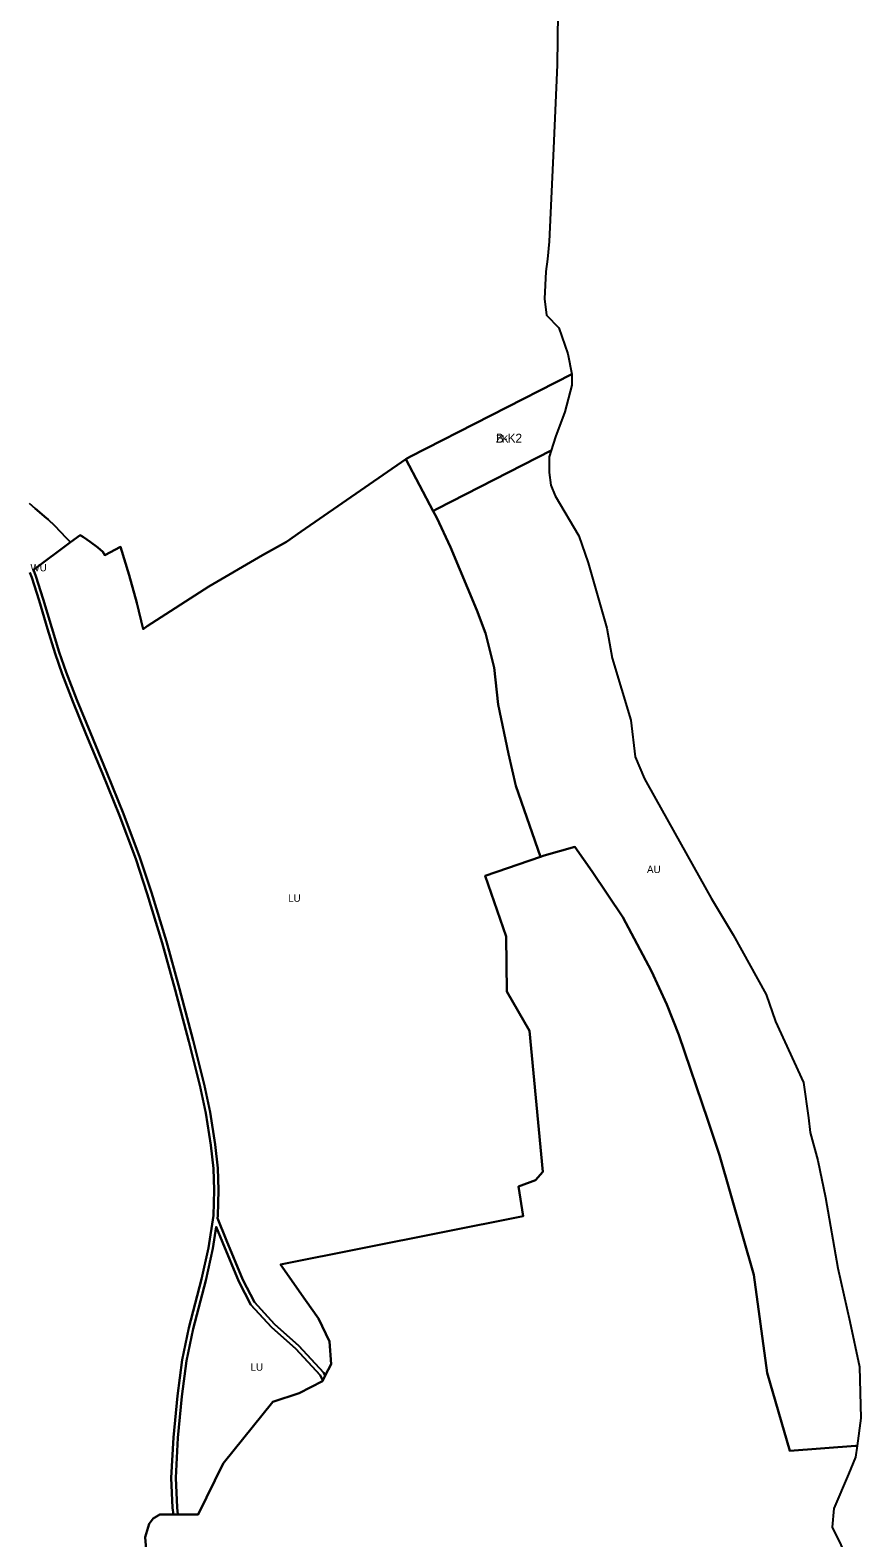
# Model space of a CAD drawing. Extents: x -532067 to -529270, y -1180561 to -1176456.
# Drawn here: x -530157 to -529591, y -1180006 to -1178979 of the extents above; entities that cross this region are included whole.
import ezdxf

# ---------------------------------------------------------------- set-up
doc = ezdxf.new("R2010")
doc.units = 0
for name, color, linetype in [('90630013', 7, 'Continuous'), ('90710023', 7, 'Continuous'), ('90730013', 7, 'Continuous'), ('90750013', 7, 'Continuous'), ('90770013', 7, 'Continuous'), ('ID_navrh', 7, 'Continuous')]:
    doc.layers.add(name, color=color, linetype=linetype)

msp = doc.modelspace()

# ---------------------------------------------------------------- linework, layer by layer
at = {"layer": '90630013'}
msp.add_lwpolyline([(-530157.9403, -1179301.39145), (-530153.9193, -1179304.64945), (-530151.1353, -1179307.13145), (-530147.5963, -1179310.16545), (-530145.0753, -1179312.33345), (-530140.6333, -1179316.66945), (-530132.8283, -1179324.73845), (-530129.9333, -1179327.73145), (-530155.1743, -1179346.45045), (-530153.5473, -1179350.79245), (-530148.4673, -1179366.46045), (-530142.7323, -1179386.00945), (-530137.6503, -1179402.66845), (-530132.8233, -1179416.41845), (-530125.5443, -1179435.13045), (-530116.4203, -1179457.56345), (-530105.4193, -1179484.13845), (-530093.7863, -1179512.92945), (-530082.6913, -1179542.63745), (-530074.7343, -1179566.39445), (-530064.6193, -1179599.92445), (-530055.7123, -1179632.12945), (-530046.3623, -1179667.39345), (-530038.9243, -1179697.16745), (-530034.8343, -1179716.32245), (-530031.2413, -1179738.26245), (-530029.5813, -1179754.37545), (-530028.9503, -1179769.45045), (-530029.5843, -1179786.84445), (-530029.8413, -1179788.59645), (-530023.5823, -1179803.73845), (-530012.5283, -1179830.47545), (-530004.4723, -1179845.81445), (-529990.8993, -1179860.67845), (-529974.2853, -1179875.42845), (-529957.5543, -1179893.62445), (-529956.3333, -1179895.84545), (-529958.0503, -1179899.12645), (-529959.1613, -1179896.89645), (-529959.7993, -1179895.61645), (-529976.3913, -1179877.57045), (-529993.0093, -1179862.81845), (-530006.9483, -1179847.55245), (-530015.2483, -1179831.74945), (-530026.3543, -1179804.88445), (-530030.6903, -1179794.39445), (-530032.8693, -1179809.26545), (-530037.7973, -1179830.89445), (-530046.2823, -1179864.04145), (-530050.8573, -1179885.68545), (-530054.0183, -1179910.00545), (-530056.7063, -1179938.14145), (-530058.2353, -1179965.53245), (-530057.3423, -1179985.65445), (-530056.7433, -1179990.50045), (-530059.7683, -1179990.48145), (-530060.3343, -1179985.90445), (-530061.2393, -1179965.51445), (-530059.6983, -1179937.91545), (-530057.0003, -1179909.66945), (-530053.8173, -1179885.18145), (-530049.2043, -1179863.35945), (-530040.7133, -1179830.18845), (-530035.8213, -1179808.71345), (-530032.5763, -1179786.57245), (-530031.9523, -1179769.45845), (-530032.5753, -1179754.59145), (-530034.2173, -1179738.65845), (-530037.7823, -1179716.87845), (-530041.8483, -1179697.84545), (-530049.2683, -1179668.14145), (-530058.6083, -1179632.91345), (-530067.5013, -1179600.75845), (-530077.5943, -1179567.30445), (-530085.5193, -1179543.63945), (-530096.5823, -1179514.01545), (-530108.1953, -1179485.27445), (-530119.1963, -1179458.70145), (-530128.3323, -1179436.23845), (-530135.6373, -1179417.45845), (-530140.5023, -1179403.60245), (-530145.6063, -1179386.86945), (-530151.3333, -1179367.34645), (-530156.3793, -1179351.78245), (-530157.6823, -1179348.30645)], dxfattribs=at)
at = {"layer": '90710023'}
msp.add_lwpolyline([(-529802.1983, -1179265.11945), (-529879.9973, -1179304.96045), (-529882.5483, -1179306.33145), (-529882.7653, -1179306.44845), (-529901.4753, -1179271.09245), (-529898.5783, -1179269.53645), (-529788.3023, -1179213.06445), (-529788.3023, -1179220.72845), (-529793.0853, -1179238.91945), (-529799.2923, -1179255.84645)], close=True, dxfattribs=at)
at = {"layer": '90730013'}
msp.add_lwpolyline([(-530073.5353, -1180073.74245), (-530079.0333, -1180006.03545), (-530076.2843, -1179996.88545), (-530073.5353, -1179993.22645), (-530068.9533, -1179990.48145), (-530059.7903, -1179990.48145), (-530059.7683, -1179990.48145), (-530056.7433, -1179990.50045), (-530042.9493, -1179990.59045), (-530025.8873, -1179955.71245), (-529992.1313, -1179913.72845), (-529973.9833, -1179907.85145), (-529958.2653, -1179899.53745), (-529958.0503, -1179899.12645), (-529956.3333, -1179895.84545), (-529952.2643, -1179888.07045), (-529953.3483, -1179872.56745), (-529960.9023, -1179856.89545), (-529969.6583, -1179844.49445), (-529986.8263, -1179820.03945), (-529821.3803, -1179787.17945), (-529824.6333, -1179766.87845), (-529812.8943, -1179762.56045), (-529808.0913, -1179756.82645), (-529817.0733, -1179660.68845), (-529832.5653, -1179634.03345), (-529832.8743, -1179596.53145), (-529847.4083, -1179555.25245), (-529809.6343, -1179542.09445), (-529807.1313, -1179541.25745), (-529786.1093, -1179535.39945), (-529774.2633, -1179552.13645), (-529753.4513, -1179583.38345), (-529734.0253, -1179620.05445), (-529723.3723, -1179642.89445), (-529715.3613, -1179663.43245), (-529695.4563, -1179721.60645), (-529687.4573, -1179745.53845), (-529664.1783, -1179827.02345), (-529655.1453, -1179893.84145), (-529639.6543, -1179947.08645), (-529594.9363, -1179943.75245), (-529593.7793, -1179943.66645), (-529594.8263, -1179951.36445), (-529599.7513, -1179963.03445), (-529609.7043, -1179986.32845), (-529610.7653, -1179999.24045), (-529598.9323, -1180023.30345)], dxfattribs=at)
at = {"layer": '90750013'}
msp.add_lwpolyline([(-529797.8273, -1178967.16945), (-529798.1793, -1179002.39145), (-529800.6303, -1179059.25145), (-529803.6643, -1179122.65845), (-529804.7883, -1179134.70545), (-529806.0063, -1179143.15845), (-529806.9423, -1179161.75445), (-529805.5713, -1179172.90345), (-529797.1663, -1179181.64045), (-529791.0533, -1179199.42245), (-529788.3023, -1179213.06445), (-529898.5783, -1179269.53645), (-529901.4753, -1179271.09245), (-529972.7423, -1179320.39245), (-529982.7213, -1179327.40045), (-529999.0633, -1179336.53645), (-530035.7073, -1179357.84445), (-530077.6063, -1179385.04845), (-530080.4813, -1179386.91445), (-530084.6183, -1179369.12645), (-530090.0503, -1179350.21445), (-530095.8023, -1179330.98145), (-530106.5343, -1179336.66245), (-530107.9753, -1179334.25345), (-530111.2173, -1179331.36345), (-530116.6203, -1179327.38845), (-530121.1823, -1179324.37745), (-530123.4633, -1179322.93245), (-530129.9333, -1179327.73145), (-530132.8283, -1179324.73845), (-530140.6333, -1179316.66945), (-530145.0753, -1179312.33345), (-530147.5963, -1179310.16545), (-530151.1353, -1179307.13145), (-530153.9193, -1179304.64945), (-530157.9403, -1179301.39145)], dxfattribs=at)
msp.add_lwpolyline([(-529731.0603, -1179502.81145), (-529693.3403, -1179570.28245), (-529678.1743, -1179595.35845), (-529655.8273, -1179635.92545), (-529649.3253, -1179654.34145), (-529630.2493, -1179696.04845), (-529627.0133, -1179720.04245), (-529625.7463, -1179730.20545), (-529620.5403, -1179749.25945), (-529615.2783, -1179774.41745), (-529606.8593, -1179822.60145), (-529598.6743, -1179859.02145), (-529592.2033, -1179889.92345), (-529591.2253, -1179924.87345), (-529593.7793, -1179943.66645), (-529594.9363, -1179943.75245), (-529639.6543, -1179947.08645), (-529655.1453, -1179893.84145), (-529664.1783, -1179827.02345), (-529687.4573, -1179745.53845), (-529695.4563, -1179721.60645), (-529715.3613, -1179663.43245), (-529723.3723, -1179642.89445), (-529734.0253, -1179620.05445), (-529753.4513, -1179583.38345), (-529774.2633, -1179552.13645), (-529786.1093, -1179535.39945), (-529807.1313, -1179541.25745), (-529809.6343, -1179542.09445), (-529826.4563, -1179493.80045), (-529831.3913, -1179472.07145), (-529838.5203, -1179438.24045), (-529841.2623, -1179413.21145), (-529847.0203, -1179389.83145), (-529852.9773, -1179374.00745), (-529870.9293, -1179331.00845), (-529880.2713, -1179311.16145), (-529882.7653, -1179306.44845), (-529882.5483, -1179306.33145), (-529879.9973, -1179304.96045), (-529802.1983, -1179265.11945), (-529803.5603, -1179269.46645), (-529803.7543, -1179280.16645), (-529802.5903, -1179288.72745), (-529799.6803, -1179296.12145), (-529783.3873, -1179323.35945), (-529777.1383, -1179341.82345), (-529764.4693, -1179386.20145), (-529760.7663, -1179406.72845), (-529748.0053, -1179449.03145), (-529744.9693, -1179474.04845), (-529738.6163, -1179489.09745)], close=True, dxfattribs=at)
at = {"layer": '90770013'}
for points in [[(-529852.9773, -1179374.00745), (-529847.0203, -1179389.83145), (-529841.2623, -1179413.21145), (-529838.5203, -1179438.24045), (-529831.3913, -1179472.07145), (-529826.4563, -1179493.80045), (-529809.6343, -1179542.09445), (-529847.4083, -1179555.25245), (-529832.8743, -1179596.53145), (-529832.5653, -1179634.03345), (-529817.0733, -1179660.68845), (-529808.0913, -1179756.82645), (-529812.8943, -1179762.56045), (-529824.6333, -1179766.87845), (-529821.3803, -1179787.17945), (-529986.8263, -1179820.03945), (-529969.6583, -1179844.49445), (-529960.9023, -1179856.89545), (-529953.3483, -1179872.56745), (-529952.2643, -1179888.07045), (-529956.3333, -1179895.84545), (-529957.5543, -1179893.62445), (-529974.2853, -1179875.42845), (-529990.8993, -1179860.67845), (-530004.4723, -1179845.81445), (-530012.5283, -1179830.47545), (-530023.5823, -1179803.73845), (-530029.8413, -1179788.59645), (-530029.5843, -1179786.84445), (-530028.9503, -1179769.45045), (-530029.5813, -1179754.37545), (-530031.2413, -1179738.26245), (-530034.8343, -1179716.32245), (-530038.9243, -1179697.16745), (-530046.3623, -1179667.39345), (-530055.7123, -1179632.12945), (-530064.6193, -1179599.92445), (-530074.7343, -1179566.39445), (-530082.6913, -1179542.63745), (-530093.7863, -1179512.92945), (-530105.4193, -1179484.13845), (-530116.4203, -1179457.56345), (-530125.5443, -1179435.13045), (-530132.8233, -1179416.41845), (-530137.6503, -1179402.66845), (-530142.7323, -1179386.00945), (-530148.4673, -1179366.46045), (-530153.5473, -1179350.79245), (-530155.1743, -1179346.45045), (-530129.9333, -1179327.73145), (-530123.4633, -1179322.93245), (-530121.1823, -1179324.37745), (-530116.6203, -1179327.38845), (-530111.2173, -1179331.36345), (-530107.9753, -1179334.25345), (-530106.5343, -1179336.66245), (-530095.8023, -1179330.98145), (-530090.0503, -1179350.21445), (-530084.6183, -1179369.12645), (-530080.4813, -1179386.91445), (-530077.6063, -1179385.04845), (-530035.7073, -1179357.84445), (-529999.0633, -1179336.53645), (-529982.7213, -1179327.40045), (-529972.7423, -1179320.39245), (-529901.4753, -1179271.09245), (-529882.7653, -1179306.44845), (-529880.2713, -1179311.16145), (-529870.9293, -1179331.00845)], [(-530025.8873, -1179955.71245), (-530042.9493, -1179990.59045), (-530056.7433, -1179990.50045), (-530057.3423, -1179985.65445), (-530058.2353, -1179965.53245), (-530056.7063, -1179938.14145), (-530054.0183, -1179910.00545), (-530050.8573, -1179885.68545), (-530046.2823, -1179864.04145), (-530037.7973, -1179830.89445), (-530032.8693, -1179809.26545), (-530030.6903, -1179794.39445), (-530026.3543, -1179804.88445), (-530015.2483, -1179831.74945), (-530006.9483, -1179847.55245), (-529993.0093, -1179862.81845), (-529976.3913, -1179877.57045), (-529959.7993, -1179895.61645), (-529959.1613, -1179896.89645), (-529958.0503, -1179899.12645), (-529958.2653, -1179899.53745), (-529973.9833, -1179907.85145), (-529992.1313, -1179913.72845)]]:
    msp.add_lwpolyline(points, close=True, dxfattribs=at)
msp.add_lwpolyline([(-530157.6823, -1179348.30645), (-530156.3793, -1179351.78245), (-530151.3333, -1179367.34645), (-530145.6063, -1179386.86945), (-530140.5023, -1179403.60245), (-530135.6373, -1179417.45845), (-530128.3323, -1179436.23845), (-530119.1963, -1179458.70145), (-530108.1953, -1179485.27445), (-530096.5823, -1179514.01545), (-530085.5193, -1179543.63945), (-530077.5943, -1179567.30445), (-530067.5013, -1179600.75845), (-530058.6083, -1179632.91345), (-530049.2683, -1179668.14145), (-530041.8483, -1179697.84545), (-530037.7823, -1179716.87845), (-530034.2173, -1179738.65845), (-530032.5753, -1179754.59145), (-530031.9523, -1179769.45845), (-530032.5763, -1179786.57245), (-530035.8213, -1179808.71345), (-530040.7133, -1179830.18845), (-530049.2043, -1179863.35945), (-530053.8173, -1179885.18145), (-530057.0003, -1179909.66945), (-530059.6983, -1179937.91545), (-530061.2393, -1179965.51445), (-530060.3343, -1179985.90445), (-530059.7683, -1179990.48145), (-530059.7903, -1179990.48145), (-530068.9533, -1179990.48145), (-530073.5353, -1179993.22645), (-530076.2843, -1179996.88545), (-530079.0333, -1180006.03545), (-530073.5353, -1180073.74245)], dxfattribs=at)

# ---------------------------------------------------------------- texts
at = {"layer": '90630013'}
msp.add_text('WU', height=5, rotation=359.99999997, dxfattribs=at).set_placement((-530157.23117, -1179347.55795))
at = {"layer": '90710023'}
msp.add_text('ZK', height=5, rotation=359.99999999, dxfattribs=at).set_placement((-529839.99899, -1179259.75645))
at = {"layer": '90750013'}
msp.add_text('AU', height=5, rotation=359.99999999, dxfattribs=at).set_placement((-529736.9953, -1179553.24372))
at = {"layer": '90770013'}
for rotation, p in [(0.00000007, (-529981.6328, -1179572.82198)), (359.99999998, (-530007.20682, -1179892.49245))]:
    msp.add_text('LU', height=5, rotation=rotation, dxfattribs=at).set_placement(p)
at = {"layer": 'ID_navrh'}
msp.add_text('B-K2', height=6, rotation=0.00000001, dxfattribs=at).set_placement((-529839.99899, -1179259.75645))

doc.saveas('drawing.dxf')
